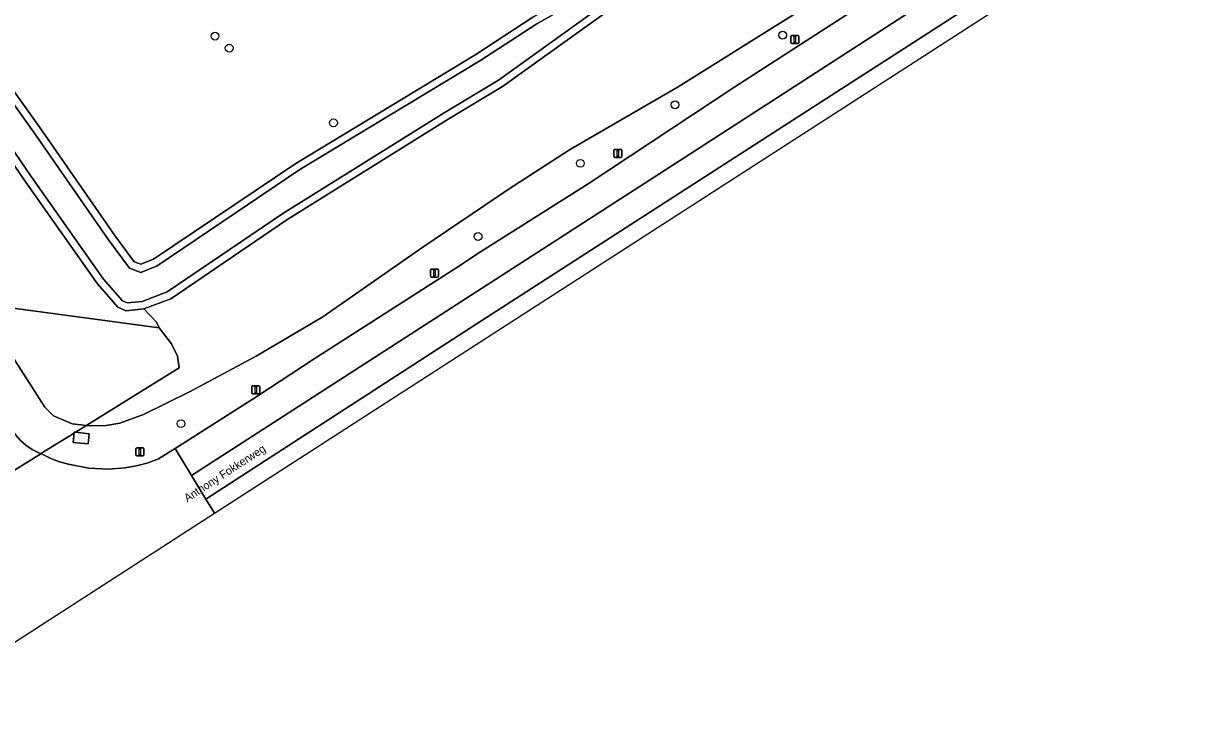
# Model space of a CAD drawing. Extents: x 156141 to 158132, y 385651 to 388333.
# Drawn here: x 156566.6 to 156713.1, y 385669.9 to 385757.9 of the extents above; entities that cross this region are included whole.
import ezdxf

# ---------------------------------------------------------------- set-up
doc = ezdxf.new("R2010")
doc.units = 0
for name, color, linetype in [('IMGEO_Berm_groen', 7, 'Continuous'), ('IMGEO_Boom', 7, 'Continuous'), ('IMGEO_Grasland_overig', 7, 'Continuous'), ('IMGEO_Groenvoorziening', 7, 'Continuous'), ('IMGEO_Lichtmast', 7, 'Continuous'), ('IMGEO_Loofbos', 7, 'Continuous'), ('IMGEO_Oever', 7, 'Continuous'), ('IMGEO_Openbare_ruimte_label', 7, 'Continuous'), ('IMGEO_Rijbaan_autosnelweg', 7, 'Continuous'), ('IMGEO_Rijbaan_regionaal_gesloten', 7, 'Continuous'), ('IMGEO_Terreindeel_open', 7, 'Continuous'), ('IMGEO_Verkeersregelinstallatiepaal', 7, 'Continuous'), ('IMGEO_Waterloop', 7, 'Continuous')]:
    doc.layers.add(name, color=color, linetype=linetype)

msp = doc.modelspace()

# ---------------------------------------------------------------- linework, layer by layer
at = {"layer": 'IMGEO_Berm_groen'}
for points in [[(156722.04, 385796.11), (156648.45, 385750), (156634.88, 385742.14), (156627.32, 385737.27), (156616.43, 385729.88), (156604.05, 385721.26), (156595.72, 385716.34), (156587.37, 385711.88), (156581.64, 385709.05), (156578.7, 385707.99), (156576.98, 385707.68), (156574.94, 385707.65), (156574.56, 385707.69), (156574.54, 385707.71), (156574.52, 385707.69), (156573.13, 385706.83), (156574.87, 385706.64), (156574.74, 385705.37), (156572.84, 385705.57), (156572.96, 385706.73), (156568.83, 385704.16), (156570.08, 385703.57), (156571.16, 385703.14), (156572.26, 385702.84), (156574.82, 385702.36), (156577.22, 385702.24), (156579.33, 385702.4), (156580.93, 385702.68), (156582.23, 385703.01), (156583.53, 385703.53), (156585.58, 385704.82), (156595.81, 385711.32), (156602.95, 385716), (156621.24, 385727.71)], [(156621.24, 385727.71), (156623.41, 385729.19), (156637.21, 385737.87), (156655.52, 385750), (156674.51, 385762.32)]]:
    msp.add_lwpolyline(points, dxfattribs=at)
msp.add_lwpolyline([(156574.52, 385707.69), (156572.74, 385707.89), (156570.38, 385708.89), (156569.31, 385709.98), (156567.67, 385712.53), (156565.03, 385716.69), (156560.99, 385722.91), (156558.02, 385718.93), (156562.12, 385712.22), (156564.59, 385708.05), (156565.69, 385706.46), (156566.26, 385705.79), (156566.93, 385705.21), (156567.73, 385704.69), (156568.82, 385704.15), (156568.83, 385704.16), (156572.96, 385706.73), (156572.97, 385706.85), (156573.13, 385706.83)], close=True, dxfattribs=at)
at = {"layer": 'IMGEO_Boom'}
for centre in [(156590.57, 385756.35), (156661.49, 385756.47), (156592.35, 385754.85), (156648.04, 385747.76), (156605.38, 385745.51), (156636.21, 385740.45), (156623.44, 385731.31), (156586.33, 385707.91)]:
    msp.add_circle(centre, 0.489, dxfattribs=at)
at = {"layer": 'IMGEO_Grasland_overig'}
msp.add_lwpolyline([(156560.99, 385722.91), (156583.59, 385719.9), (156583.27, 385720.6), (156581.7, 385722.26), (156579.43, 385722.03), (156578.44, 385722.48), (156575.91, 385725.4), (156566.81, 385738.25), (156557.07, 385752.53)], dxfattribs=at)
msp.add_lwpolyline([(156560.99, 385722.91), (156565.03, 385716.69), (156567.67, 385712.53), (156569.31, 385709.98), (156570.38, 385708.89), (156572.74, 385707.89), (156574.52, 385707.69), (156574.54, 385707.71), (156586.11, 385714.89), (156585.89, 385716.34), (156585.15, 385717.9), (156583.59, 385719.9)], close=True, dxfattribs=at)
at = {"layer": 'IMGEO_Groenvoorziening'}
msp.add_lwpolyline([(156485.36, 385863.5), (156508.5, 385830.03), (156524.15, 385808.03), (156534.49, 385793.28), (156543.71, 385780.55), (156550.98, 385769.74), (156568.68, 385744.93), (156578.04, 385731.44), (156580.47, 385728.12), (156581.29, 385727.83), (156582.88, 385728.49), (156600.68, 385740.45), (156623.14, 385754.05), (156630.27, 385758.7), (156662.71, 385777.13), (156698.81, 385796.2)], dxfattribs=at)
at = {"layer": 'IMGEO_Lichtmast'}
for p, q in [((156662.51, 385755.53), (156662.51, 385756.33)), ((156662.51, 385756.33), (156662.51, 385755.53)), ((156662.61, 385756.43), (156663.4, 385756.43)), ((156663.4, 385756.43), (156662.61, 385756.43)), ((156663.5, 385756.33), (156663.5, 385755.53)), ((156663.5, 385755.53), (156663.5, 385756.33)), ((156663.4, 385755.43), (156662.61, 385755.43)), ((156662.61, 385755.43), (156663.4, 385755.43)), ((156640.41, 385741.3), (156640.41, 385742.1)), ((156640.41, 385742.1), (156640.41, 385741.3)), ((156640.51, 385742.2), (156641.3, 385742.2)), ((156641.3, 385742.2), (156640.51, 385742.2)), ((156641.4, 385742.1), (156641.4, 385741.3)), ((156641.4, 385741.3), (156641.4, 385742.1)), ((156641.3, 385741.2), (156640.51, 385741.2)), ((156640.51, 385741.2), (156641.3, 385741.2)), ((156617.5, 385726.34), (156617.5, 385727.14)), ((156617.5, 385727.14), (156617.5, 385726.34)), ((156617.6, 385727.24), (156618.39, 385727.24)), ((156618.39, 385727.24), (156617.6, 385727.24)), ((156618.49, 385727.14), (156618.49, 385726.34)), ((156618.49, 385726.34), (156618.49, 385727.14)), ((156618.39, 385726.24), (156617.6, 385726.24)), ((156617.6, 385726.24), (156618.39, 385726.24)), ((156595.17, 385711.74), (156595.17, 385712.54)), ((156595.17, 385712.54), (156595.17, 385711.74)), ((156595.27, 385712.64), (156596.06, 385712.64)), ((156596.06, 385712.64), (156595.27, 385712.64)), ((156596.16, 385712.54), (156596.16, 385711.74)), ((156596.16, 385711.74), (156596.16, 385712.54)), ((156596.06, 385711.64), (156595.27, 385711.64)), ((156595.27, 385711.64), (156596.06, 385711.64))]:
    msp.add_line(p, q, dxfattribs=at)
for points in [[(156662.93, 385756.3), (156663.08, 385756.3), (156663.08, 385755.55), (156662.93, 385755.55), (156662.93, 385756.3)], [(156640.83, 385742.07), (156640.98, 385742.07), (156640.98, 385741.32), (156640.83, 385741.32), (156640.83, 385742.07)], [(156617.92, 385727.12), (156618.07, 385727.12), (156618.07, 385726.37), (156617.92, 385726.37), (156617.92, 385727.12)], [(156595.59, 385712.52), (156595.74, 385712.52), (156595.74, 385711.77), (156595.59, 385711.77), (156595.59, 385712.52)]]:
    msp.add_lwpolyline(points, dxfattribs=at)
for centre, start, end in [((156662.61, 385756.33), 90, 180), ((156662.61, 385756.33), 90, 180), ((156663.4, 385756.33), 0, 90), ((156663.4, 385756.33), 360, 90), ((156662.61, 385755.53), 180, 270), ((156662.61, 385755.53), 180, 270), ((156663.4, 385755.53), 270, 0), ((156663.4, 385755.53), 270, 0), ((156640.51, 385742.1), 90, 180), ((156640.51, 385742.1), 90, 180), ((156640.51, 385741.3), 180, 270), ((156640.51, 385741.3), 180, 270), ((156641.3, 385742.1), 0, 90), ((156641.3, 385742.1), 360, 90), ((156641.3, 385741.3), 270, 0), ((156641.3, 385741.3), 270, 0), ((156617.6, 385727.14), 90, 180), ((156617.6, 385727.14), 90, 180), ((156618.39, 385727.14), 0, 90), ((156618.39, 385727.14), 360, 90), ((156617.6, 385726.34), 180, 270), ((156617.6, 385726.34), 180, 270), ((156618.39, 385726.34), 270, 0), ((156618.39, 385726.34), 270, 0), ((156595.27, 385712.54), 90, 180), ((156595.27, 385712.54), 90, 180), ((156596.06, 385712.54), 0, 90), ((156596.06, 385712.54), 360, 90), ((156595.27, 385711.74), 180, 270), ((156595.27, 385711.74), 180, 270), ((156596.06, 385711.74), 270, 0), ((156596.06, 385711.74), 270, 0)]:
    msp.add_arc(centre, 0.1, start, end, dxfattribs=at)
at = {"layer": 'IMGEO_Loofbos'}
msp.add_lwpolyline([(156645.72, 385763.88), (156626.51, 385750.04), (156619.71, 385745.98), (156599.56, 385733.38), (156585.04, 385723.52), (156581.7, 385722.26), (156583.27, 385720.6), (156583.59, 385719.9), (156585.15, 385717.9), (156585.89, 385716.34), (156586.11, 385714.89), (156574.54, 385707.71), (156574.56, 385707.69), (156574.94, 385707.65), (156576.98, 385707.68), (156578.7, 385707.99), (156581.64, 385709.05), (156587.37, 385711.88), (156595.72, 385716.34), (156604.05, 385721.26), (156616.43, 385729.88), (156627.32, 385737.27), (156634.88, 385742.14), (156648.45, 385750), (156722.04, 385796.11)], dxfattribs=at)
at = {"layer": 'IMGEO_Oever'}
for points in [[(156757.02, 385826.8), (156712.71, 385801.26), (156678.99, 385783.31), (156645.21, 385764.67), (156625.99, 385750.83), (156619.21, 385746.78), (156599.04, 385734.17), (156584.6, 385724.37), (156581.48, 385723.19), (156579.58, 385723), (156579.01, 385723.25), (156576.66, 385725.99), (156567.59, 385738.79), (156557.85, 385753.07)], [(156550.2, 385769.2), (156567.91, 385744.39), (156577.27, 385730.89), (156579.88, 385727.33), (156581.32, 385726.82), (156583.33, 385727.65), (156601.19, 385739.66), (156623.65, 385753.25), (156630.77, 385757.9), (156663.17, 385776.3), (156699.26, 385795.37), (156718.29, 385806.04)], [(156717.81, 385806.86), (156698.81, 385796.2), (156662.71, 385777.13), (156630.27, 385758.7), (156623.14, 385754.05), (156600.68, 385740.45), (156582.88, 385728.49), (156581.29, 385727.83), (156580.47, 385728.12), (156578.04, 385731.44), (156568.68, 385744.93), (156550.98, 385769.74)], [(156557.07, 385752.53), (156566.81, 385738.25), (156575.91, 385725.4), (156578.44, 385722.48), (156579.43, 385722.03), (156581.7, 385722.26), (156585.04, 385723.52), (156599.56, 385733.38), (156619.71, 385745.98), (156626.51, 385750.04), (156645.72, 385763.88), (156679.44, 385782.48), (156713.17, 385800.43)]]:
    msp.add_lwpolyline(points, dxfattribs=at)
at = {"layer": 'IMGEO_Rijbaan_autosnelweg'}
msp.add_lwpolyline([(156568.82, 385704.15), (156567.73, 385704.69), (156566.93, 385705.21), (156566.26, 385705.79), (156565.69, 385706.46), (156564.59, 385708.05), (156562.12, 385712.22), (156558.02, 385718.93), (156557.63, 385718.34), (156555.02, 385715.31), (156550.94, 385714.81), (156551.41, 385712.96), (156555.05, 385706.99), (156558, 385701.77), (156558.79, 385700.09), (156559.39, 385698.56), (156559.46, 385698.34), (156564.65, 385701.56)], close=True, dxfattribs=at)
at = {"layer": 'IMGEO_Rijbaan_regionaal_gesloten'}
for points in [[(156713.93, 385783.6), (156706.05, 385778.62), (156701.01, 385774.68), (156649.33, 385741.23), (156587.63, 385701.45), (156589.43, 385698.49), (156597.58, 385703.76), (156623.93, 385720.8), (156658.56, 385743.14), (156695.36, 385766.89), (156719.79, 385782.67)], [(156719.79, 385782.67), (156695.36, 385766.89), (156658.56, 385743.14), (156623.93, 385720.8), (156597.58, 385703.76), (156589.43, 385698.49), (156590.51, 385696.73), (156722.7, 385782.03)], [(156674.51, 385762.32), (156655.52, 385750), (156637.21, 385737.87), (156623.41, 385729.19), (156621.24, 385727.71), (156602.95, 385716), (156595.81, 385711.32), (156585.58, 385704.82), (156587.63, 385701.45), (156649.33, 385741.23), (156701.01, 385774.68)], [(156548.97, 385669.92), (156590.51, 385696.73), (156589.43, 385698.49), (156587.63, 385701.45), (156585.58, 385704.82), (156583.53, 385703.53), (156582.23, 385703.01), (156580.93, 385702.68), (156579.33, 385702.4), (156577.22, 385702.24), (156574.82, 385702.36), (156572.26, 385702.84), (156571.16, 385703.14), (156570.08, 385703.57), (156568.83, 385704.16), (156568.82, 385704.15), (156564.65, 385701.56)]]:
    msp.add_lwpolyline(points, dxfattribs=at)
at = {"layer": 'IMGEO_Terreindeel_open'}
msp.add_lwpolyline([(156574.87, 385706.64), (156573.13, 385706.83), (156572.97, 385706.85), (156572.96, 385706.73), (156572.84, 385705.57), (156574.74, 385705.37)], close=True, dxfattribs=at)
at = {"layer": 'IMGEO_Verkeersregelinstallatiepaal'}
for p, q in [((156580.69, 385703.99), (156580.69, 385704.79)), ((156580.69, 385704.79), (156580.69, 385703.99)), ((156580.79, 385704.89), (156581.58, 385704.89)), ((156581.58, 385704.89), (156580.79, 385704.89)), ((156581.68, 385704.79), (156581.68, 385703.99)), ((156581.68, 385703.99), (156581.68, 385704.79)), ((156581.58, 385703.89), (156580.79, 385703.89)), ((156580.79, 385703.89), (156581.58, 385703.89))]:
    msp.add_line(p, q, dxfattribs=at)
msp.add_lwpolyline([(156581.11, 385704.77), (156581.26, 385704.77), (156581.26, 385704.02), (156581.11, 385704.02), (156581.11, 385704.77)], dxfattribs=at)
for centre, start, end in [((156580.79, 385704.79), 90, 180), ((156580.79, 385704.79), 90, 180), ((156581.58, 385704.79), 0, 90), ((156581.58, 385704.79), 360, 90), ((156580.79, 385703.99), 180, 270), ((156580.79, 385703.99), 180, 270), ((156581.58, 385703.99), 270, 0), ((156581.58, 385703.99), 270, 0)]:
    msp.add_arc(centre, 0.1, start, end, dxfattribs=at)
at = {"layer": 'IMGEO_Waterloop'}
for points in [[(156557.85, 385753.07), (156567.59, 385738.79), (156576.66, 385725.99), (156579.01, 385723.25), (156579.58, 385723), (156581.48, 385723.19), (156584.6, 385724.37), (156599.04, 385734.17), (156619.21, 385746.78), (156625.99, 385750.83), (156645.21, 385764.67), (156678.99, 385783.31), (156712.71, 385801.26), (156757.02, 385826.8)], [(156718.29, 385806.04), (156699.26, 385795.37), (156663.17, 385776.3), (156630.77, 385757.9), (156623.65, 385753.25), (156601.19, 385739.66), (156583.33, 385727.65), (156581.32, 385726.82), (156579.88, 385727.33), (156577.27, 385730.89), (156567.91, 385744.39), (156550.2, 385769.2)]]:
    msp.add_lwpolyline(points, dxfattribs=at)

# ---------------------------------------------------------------- texts
at = {"layer": 'IMGEO_Openbare_ruimte_label'}
msp.add_text('Anthony Fokkerweg', height=1, rotation=33.1656, dxfattribs=at).set_placement((156587.11, 385698.07))

doc.saveas('drawing.dxf')
